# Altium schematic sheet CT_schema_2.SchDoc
size 276 x 169 mm
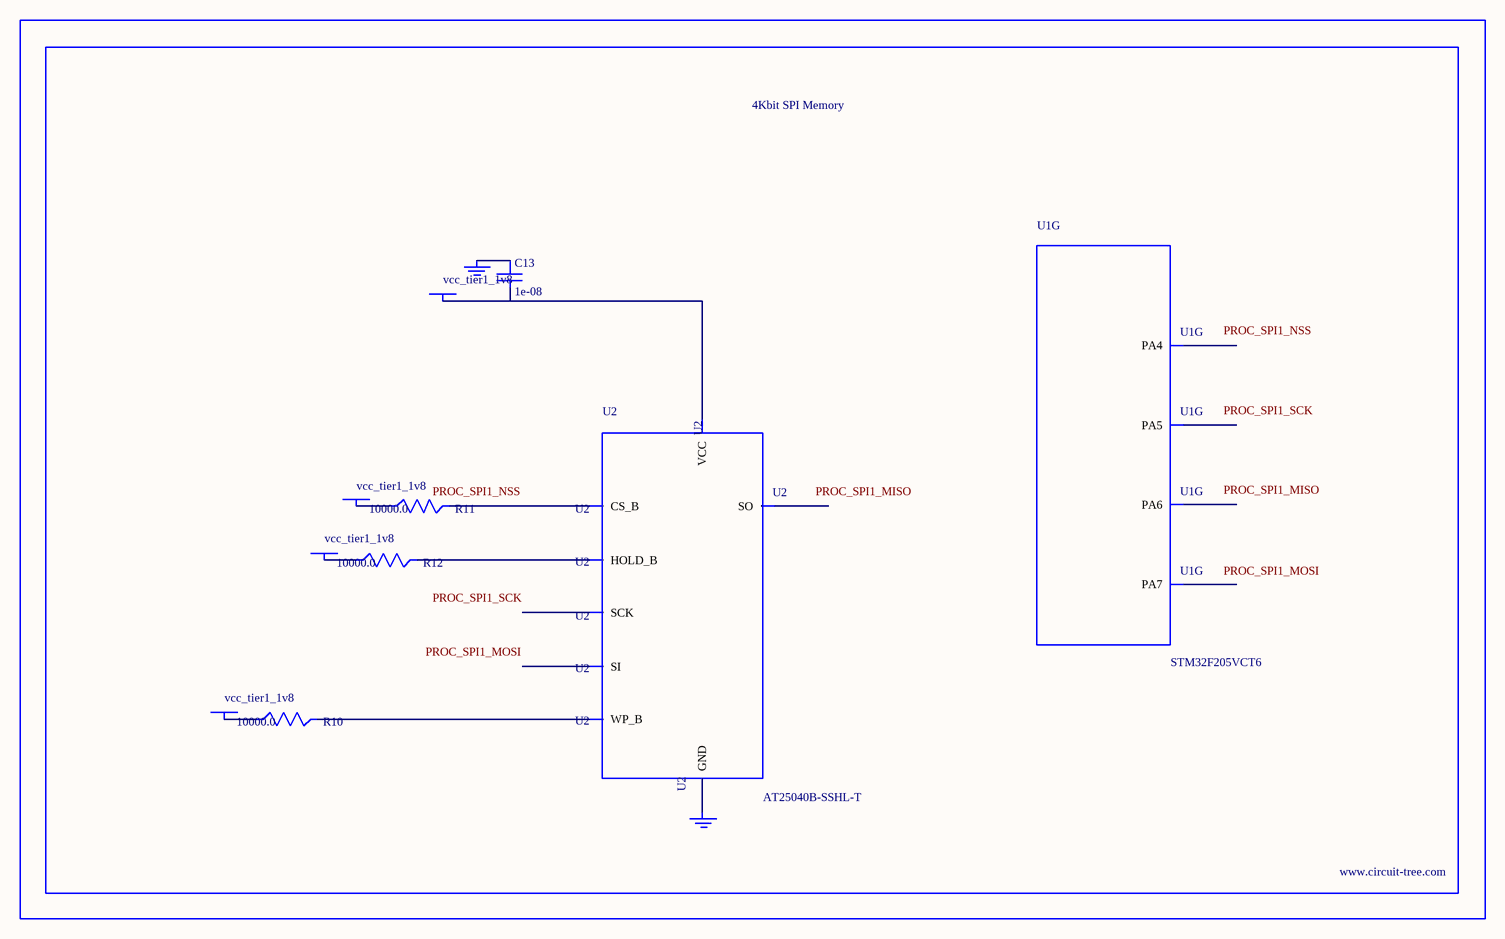
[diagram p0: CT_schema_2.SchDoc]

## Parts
BORDER1  (no value)
C13  1e-08  [C0402]
GND_INSTANCE_1_0  (no value)
GND_INSTANCE_1_1  (no value)
POWER_INSTANCE_1_0  vcc_tier1_1v8
POWER_INSTANCE_1_1  vcc_tier1_1v8
POWER_INSTANCE_1_2  vcc_tier1_1v8
POWER_INSTANCE_1_3  vcc_tier1_1v8
R10  10000.0  [R0603]
R11  10000.0  [R0603]
R12  10000.0  [R0603]
U1  STM32F205VCT6  [LQFP100]  (part G of 10)
U2  AT25040B-SSHL-T  [SOIC-8]

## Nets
NetC13_1: C13.1 GND_INSTANCE_1_0.0(GND)
NetC13_2: C13.2 POWER_INSTANCE_1_3.0(PWR) U2.8(VCC)
NetGND_INSTANCE_1_1_0: GND_INSTANCE_1_1.0(GND) U2.4(GND)
NetPOWER_INSTANCE_1_0_0: POWER_INSTANCE_1_0.0(PWR) R11.1
NetPOWER_INSTANCE_1_1_0: POWER_INSTANCE_1_1.0(PWR) R10.1
NetPOWER_INSTANCE_1_2_0: POWER_INSTANCE_1_2.0(PWR) R12.1
NetR10_2: R10.2 U2.3(WP_B)
NetR11_2: R11.2 U2.1(CS_B)
NetR12_2: R12.2 U2.7(HOLD_B)

Not connected (* = marked no-connect by the designer): U1 29(PA4) 30(PA5) 31(PA6) 32(PA7); U2 2(SO) 5(SI) 6(SCK)

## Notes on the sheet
- Labels drawn without touching a wire or pin: PROC_SPI1_MISO, PROC_SPI1_MOSI, PROC_SPI1_NSS, PROC_SPI1_SCK

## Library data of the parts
BORDER1 = BORDER_PAGE1
C13 = C0402C103K3RAC
GND_INSTANCE_1_0 GND_INSTANCE_1_1 = GND
POWER_INSTANCE_1_0-POWER_INSTANCE_1_3 = PWR
R10-R12 = RC0603JR-0710KL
